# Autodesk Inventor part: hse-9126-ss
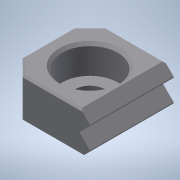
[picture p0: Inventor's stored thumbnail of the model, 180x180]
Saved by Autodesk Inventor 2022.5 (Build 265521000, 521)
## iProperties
Created: 2016-12
Part Number: hse-9126-ss
Material: 一般
Document SubType Name: Modeling
Designer: imaocorp
Density: 1 g/cm^3
Appearance: 既定
Author: imaocorp
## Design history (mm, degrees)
node "hse-9126-ss.x_t1"
node "hse-9126-ss"
node "Base1"
